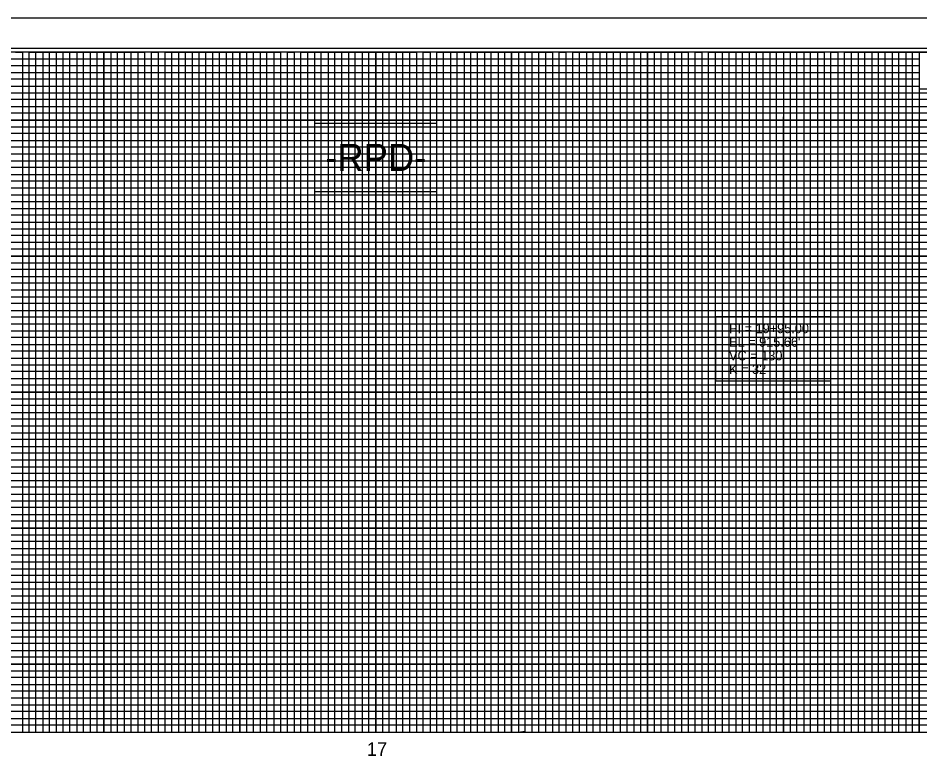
# Model space of a CAD drawing. Extents: x 1648862 to 1650889, y 802691 to 803791.
# Drawn here: x 1649516 to 1650180, y 803245 to 803791 of the extents above; entities that cross this region are included whole.
import ezdxf

# ---------------------------------------------------------------- set-up
doc = ezdxf.new("R2010")
doc.units = 0
for name, color, linetype in [('Exist Vertical Profile Horizontal Axis Label Major', 7, 'Continuous'), ('Prop Dimension Text', 7, 'Continuous'), ('Prop Grid Mask', 7, 'Continuous'), ('Prop Vertical Profile Curve Label', 7, 'Continuous'), ('Prop VPI Label', 7, 'Continuous'), ('Sheet Cutting Line CELL', 7, 'Continuous'), ('Sheet DOT Grid CELL', 7, 'Continuous'), ('Sheet Layout Profile Border Port 1', 7, 'Continuous'), ('Sheet Plot Border Inside CELL', 7, 'Continuous'), ('Sheet Plot Border Outside CELL', 7, 'Continuous'), ('Sheet Profile CELL', 7, 'Continuous'), ('Sheet Profile Grid Major CELL', 7, 'Continuous'), ('Sheet Profile Grid Middle CELL', 7, 'Continuous'), ('Sheet Profile Grid Minor CELL', 7, 'Continuous')]:
    doc.layers.add(name, color=color, linetype=linetype)

msp = doc.modelspace()

# ---------------------------------------------------------------- linework, layer by layer
at = {"layer": 'Prop Dimension Text'}
msp.add_lwpolyline([(1650179.28, 803738.96), (1650329.23, 803738.96), (1650329.23, 803766.02), (1650179.28, 803766.02)], close=True, dxfattribs=at)
at = {"layer": 'Prop Grid Mask'}
for points in [[(1649734.28, 803713.52), (1649734.28, 803663.52), (1649824.28, 803663.52), (1649824.28, 803713.52)], [(1650029.28, 803571.32), (1650029.28, 803524.32), (1650114.09, 803524.32), (1650114.09, 803571.32)]]:
    msp.add_lwpolyline(points, close=True, dxfattribs=at)
at = {"layer": 'Sheet Cutting Line CELL'}
msp.add_line((1650546.28, 803791.02), (1648862.28, 803791.02), dxfattribs=at)
at = {"layer": 'Sheet DOT Grid CELL'}
for p, q in [((1649529.28, 803266.02), (1649529.28, 803766.02)), ((1649579.28, 803266.02), (1649579.28, 803766.02)), ((1649629.28, 803266.02), (1649629.28, 803766.02)), ((1649679.28, 803266.02), (1649679.28, 803766.02)), ((1649729.28, 803266.02), (1649729.28, 803766.02)), ((1649779.28, 803266.02), (1649779.28, 803766.02)), ((1649829.28, 803266.02), (1649829.28, 803766.02)), ((1649879.28, 803266.02), (1649879.28, 803766.02)), ((1649929.28, 803266.02), (1649929.28, 803766.02)), ((1649979.28, 803266.02), (1649979.28, 803766.02)), ((1650029.28, 803266.02), (1650029.28, 803766.02)), ((1650329.23, 803716.02), (1649029.28, 803716.02)), ((1650079.28, 803266.02), (1650079.28, 803718.48)), ((1650129.28, 803266.02), (1650129.28, 803718.48)), ((1650179.28, 803266.02), (1650179.28, 803716.02)), ((1650329.23, 803666.02), (1649029.28, 803666.02)), ((1650329.28, 803616.02), (1649029.28, 803616.02)), ((1650529.28, 803566.02), (1649029.28, 803566.02)), ((1650529.28, 803516.02), (1649029.28, 803516.02)), ((1650529.28, 803466.02), (1649029.28, 803466.02)), ((1650529.28, 803416.02), (1649029.28, 803416.02)), ((1650529.28, 803366.02), (1649029.28, 803366.02)), ((1650529.28, 803316.02), (1649029.28, 803316.02))]:
    msp.add_line(p, q, dxfattribs=at)
at = {"layer": 'Sheet Layout Profile Border Port 1'}
msp.add_lwpolyline([(1649079.28, 803604.97), (1649079.28, 803266.02), (1650479.28, 803266.02), (1650479.28, 803604.97)], dxfattribs=at)
at = {"layer": 'Sheet Plot Border Inside CELL'}
msp.add_lwpolyline([(1648875.28, 802713.47), (1650541.78, 802713.47), (1650541.78, 803768.57), (1648875.28, 803768.57)], close=True, dxfattribs=at)
at = {"layer": 'Sheet Plot Border Outside CELL'}
msp.add_lwpolyline([(1648862.28, 802691.02), (1650546.28, 802691.02), (1650546.28, 803791.02), (1648862.28, 803791.02)], close=True, dxfattribs=at)
at = {"layer": 'Sheet Profile CELL'}
msp.add_line((1649029.28, 803266.02), (1650529.28, 803266.02), dxfattribs=at)
msp.add_lwpolyline([(1650529.28, 803766.02), (1649029.28, 803766.02), (1649029.28, 802716.02), (1650529.28, 802716.02)], close=True, dxfattribs=at)
at = {"layer": 'Sheet Profile Grid Major CELL'}
for points in [[(1649479.28, 803266.02), (1649529.28, 803266.02), (1649529.28, 803766.02), (1649579.28, 803766.02), (1649579.28, 803266.02), (1649629.28, 803266.02), (1649629.28, 803766.02), (1649679.28, 803766.02), (1649679.28, 803266.02), (1649729.28, 803266.02), (1649729.28, 803766.02), (1649779.28, 803766.02), (1649779.28, 803266.02), (1649829.28, 803266.02), (1649829.28, 803766.02), (1649879.28, 803766.02), (1649879.28, 803266.02), (1649929.28, 803266.02), (1649929.28, 803766.02), (1649979.28, 803766.02), (1649979.28, 803266.02), (1650029.28, 803266.02), (1650029.28, 803766.02), (1650079.28, 803766.02), (1650079.28, 803266.02), (1650129.28, 803266.02), (1650129.28, 803766.02), (1650179.28, 803766.02), (1650179.28, 803266.02), (1650229.28, 803266.02)], [(1649029.28, 803716.02), (1650329.28, 803716.02)], [(1650329.28, 803666.02), (1649029.28, 803666.02), (1649029.28, 803616.02), (1650329.28, 803616.02)], [(1650529.28, 803566.02), (1649029.28, 803566.02), (1649029.28, 803516.02), (1650529.28, 803516.02)], [(1650529.28, 803466.02), (1649029.28, 803466.02), (1649029.28, 803416.02), (1650529.28, 803416.02)], [(1650529.28, 803366.02), (1649029.28, 803366.02), (1649029.28, 803366.02), (1649029.28, 803316.02), (1650529.28, 803316.02)]]:
    msp.add_lwpolyline(points, dxfattribs=at)
at = {"layer": 'Sheet Profile Grid Middle CELL'}
msp.add_line((1649029.28, 803741.02), (1650179.28, 803741.02), dxfattribs=at)
for points in [[(1649504.28, 803266.02), (1649554.28, 803266.02), (1649554.28, 803766.02), (1649604.28, 803766.02), (1649604.28, 803266.02), (1649654.28, 803266.02), (1649654.28, 803266.02), (1649654.28, 803766.02), (1649704.28, 803766.02), (1649704.28, 803266.02), (1649754.28, 803266.02), (1649754.28, 803766.02), (1649804.28, 803766.02), (1649804.28, 803266.02), (1649854.28, 803266.02), (1649854.28, 803766.02), (1649904.28, 803766.02), (1649904.28, 803266.02), (1649954.28, 803266.02), (1649954.28, 803766.02), (1650004.28, 803766.02), (1650004.28, 803266.02), (1650054.28, 803266.02), (1650054.28, 803766.02), (1650104.28, 803766.02), (1650104.28, 803266.02), (1650154.28, 803266.02), (1650154.28, 803766.02), (1650204.28, 803766.02)], [(1650329.28, 803691.02), (1649029.28, 803691.02), (1649029.28, 803641.02), (1650329.28, 803641.02)], [(1650529.28, 803591.02), (1649029.28, 803591.02), (1649029.28, 803541.02), (1650354.28, 803541.02)], [(1650529.28, 803491.02), (1649029.28, 803491.02), (1649029.28, 803441.02), (1650529.28, 803441.02)], [(1650529.28, 803391.02), (1649029.28, 803391.02), (1649029.28, 803341.02), (1650529.28, 803341.02)], [(1650529.28, 803291.02), (1649029.28, 803291.02)]]:
    msp.add_lwpolyline(points, dxfattribs=at)
at = {"layer": 'Sheet Profile Grid Minor CELL'}
for p, q in [((1649079.28, 803761.02), (1650179.28, 803761.02)), ((1649614.28, 803766.02), (1649619.28, 803766.02)), ((1649624.28, 803766.02), (1649634.28, 803766.02)), ((1649639.28, 803766.02), (1649644.28, 803766.02)), ((1649649.28, 803766.02), (1649659.28, 803766.02)), ((1649664.28, 803766.02), (1649669.28, 803766.02)), ((1649674.28, 803766.02), (1649684.28, 803766.02)), ((1649689.28, 803766.02), (1649694.28, 803766.02)), ((1649699.28, 803766.02), (1649709.28, 803766.02)), ((1649714.28, 803766.02), (1649719.28, 803766.02)), ((1649724.28, 803766.02), (1649734.28, 803766.02)), ((1649739.28, 803766.02), (1649744.28, 803766.02)), ((1649749.28, 803766.02), (1649759.28, 803766.02)), ((1649764.28, 803766.02), (1649769.28, 803766.02)), ((1649774.28, 803766.02), (1649784.28, 803766.02)), ((1649789.28, 803766.02), (1649794.28, 803766.02)), ((1649799.28, 803766.02), (1649809.28, 803766.02)), ((1649814.28, 803766.02), (1649819.28, 803766.02)), ((1649824.28, 803766.02), (1649834.28, 803766.02)), ((1649839.28, 803766.02), (1649844.28, 803766.02)), ((1649849.28, 803766.02), (1649859.28, 803766.02)), ((1649864.28, 803766.02), (1649869.28, 803766.02)), ((1649874.28, 803766.02), (1649884.28, 803766.02)), ((1649889.28, 803766.02), (1649894.28, 803766.02)), ((1649899.28, 803766.02), (1649909.28, 803766.02)), ((1650179.28, 803755.98), (1649079.28, 803755.67)), ((1649079.28, 803751.02), (1650179.28, 803751.02)), ((1650329.23, 803631.02), (1649079.28, 803631.02)), ((1650329.28, 803626.02), (1649079.28, 803626.02)), ((1650329.28, 803621.02), (1649079.28, 803621.02)), ((1649079.28, 803611.02), (1650329.28, 803611.02)), ((1650329.28, 803606.02), (1649079.28, 803606.02)), ((1649079.28, 803601.02), (1650479.28, 803601.02)), ((1650479.28, 803581.02), (1649079.28, 803581.02)), ((1649079.28, 803576.02), (1650479.28, 803576.02)), ((1650479.28, 803556.02), (1649079.28, 803556.02)), ((1649079.28, 803551.02), (1650479.28, 803551.02)), ((1650479.28, 803531.02), (1649079.28, 803531.02)), ((1649079.28, 803526.02), (1650479.28, 803526.02)), ((1650479.28, 803521.02), (1649079.28, 803521.02)), ((1649079.28, 803511.02), (1650479.28, 803511.02)), ((1650479.28, 803506.02), (1649079.28, 803506.02)), ((1649079.28, 803501.02), (1650479.28, 803501.02)), ((1650479.28, 803496.02), (1649079.28, 803496.02)), ((1649079.28, 803486.02), (1650479.28, 803486.02)), ((1650479.28, 803481.02), (1649079.28, 803481.02)), ((1649079.28, 803476.02), (1650479.28, 803476.02)), ((1650479.28, 803471.02), (1649079.28, 803471.02)), ((1649079.28, 803461.02), (1650479.28, 803461.02)), ((1650479.28, 803456.02), (1649079.28, 803456.02)), ((1649079.28, 803451.02), (1650479.28, 803451.02)), ((1650479.28, 803446.02), (1649079.28, 803446.02)), ((1649079.28, 803436.02), (1650479.28, 803436.02)), ((1650479.28, 803431.02), (1649079.28, 803431.02)), ((1649079.28, 803426.02), (1650479.28, 803426.02)), ((1650479.28, 803421.02), (1649079.28, 803421.02)), ((1649079.28, 803411.02), (1650479.28, 803411.02)), ((1650479.28, 803406.02), (1649079.28, 803406.02)), ((1649079.28, 803401.02), (1650479.28, 803401.02)), ((1650479.28, 803396.02), (1649079.28, 803396.02)), ((1649079.28, 803386.02), (1650479.28, 803386.02)), ((1650479.28, 803381.02), (1649079.28, 803381.02)), ((1650479.28, 803376.02), (1649079.28, 803376.02)), ((1650479.28, 803371.02), (1649079.28, 803371.02)), ((1649079.28, 803361.02), (1650479.28, 803361.02)), ((1650479.28, 803356.02), (1649079.28, 803356.02)), ((1649079.28, 803351.02), (1650479.28, 803351.02)), ((1650479.28, 803346.02), (1649079.28, 803346.02)), ((1649079.28, 803336.02), (1650479.28, 803336.02)), ((1650479.28, 803331.02), (1649079.28, 803331.02)), ((1649079.28, 803326.02), (1650479.28, 803326.02)), ((1650479.28, 803321.02), (1649079.28, 803321.02)), ((1649079.28, 803311.02), (1650479.28, 803311.02)), ((1650479.28, 803306.02), (1649079.28, 803306.02)), ((1649079.28, 803301.02), (1650479.28, 803301.02)), ((1650479.28, 803296.02), (1649079.28, 803296.02)), ((1649079.28, 803286.02), (1650479.28, 803286.02)), ((1650479.28, 803281.02), (1649079.28, 803281.02)), ((1649079.28, 803276.02), (1650479.28, 803276.02)), ((1649609.28, 803266.02), (1649614.28, 803266.02)), ((1649619.28, 803266.02), (1649624.28, 803266.02)), ((1649634.28, 803266.02), (1649639.28, 803266.02)), ((1649644.28, 803266.02), (1649649.28, 803266.02)), ((1649659.28, 803266.02), (1649664.28, 803266.02)), ((1649669.28, 803266.02), (1649674.28, 803266.02)), ((1649684.28, 803266.02), (1649689.28, 803266.02)), ((1649694.28, 803266.02), (1649699.28, 803266.02)), ((1649709.28, 803266.02), (1649714.28, 803266.02)), ((1649719.28, 803266.02), (1649724.28, 803266.02)), ((1649734.28, 803266.02), (1649734.28, 803266.02)), ((1649734.28, 803266.02), (1649739.28, 803266.02)), ((1649744.28, 803266.02), (1649749.28, 803266.02)), ((1649759.28, 803266.02), (1649764.28, 803266.02)), ((1649769.28, 803266.02), (1649774.28, 803266.02)), ((1649784.28, 803266.02), (1649789.28, 803266.02)), ((1649794.28, 803266.02), (1649799.28, 803266.02)), ((1649809.28, 803266.02), (1649814.28, 803266.02)), ((1649819.28, 803266.02), (1649824.28, 803266.02)), ((1649834.28, 803266.02), (1649839.28, 803266.02)), ((1649844.28, 803266.02), (1649849.28, 803266.02)), ((1649859.28, 803266.02), (1649864.28, 803266.02)), ((1649869.28, 803266.02), (1649874.28, 803266.02)), ((1649884.28, 803266.02), (1649888.98, 803266.57)), ((1649888.98, 803266.57), (1649889.28, 803266.02)), ((1649894.28, 803266.02), (1649899.28, 803266.02)), ((1649909.28, 803266.02), (1649914.28, 803266.02)), ((1650159.28, 803266.02), (1650164.28, 803266.02))]:
    msp.add_line(p, q, dxfattribs=at)
for points in [[(1649514.28, 803766.02), (1649519.28, 803766.02), (1649519.28, 803266.02), (1649524.28, 803266.02), (1649524.28, 803766.02), (1649534.28, 803766.02), (1649534.28, 803266.02), (1649539.28, 803266.02), (1649539.28, 803766.02), (1649544.28, 803766.02), (1649544.28, 803266.02), (1649549.28, 803266.02), (1649549.28, 803766.02), (1649559.28, 803766.02), (1649559.28, 803266.02), (1649564.28, 803266.02), (1649564.28, 803766.02), (1649569.28, 803766.02), (1649569.28, 803266.02), (1649574.28, 803266.02), (1649574.28, 803766.02), (1649584.28, 803766.02), (1649584.28, 803266.02), (1649589.28, 803266.02), (1649589.28, 803766.02), (1649594.28, 803766.02), (1649594.28, 803266.02), (1649599.28, 803266.02), (1649599.28, 803766.02), (1649609.28, 803766.02)], [(1649609.28, 803766.02), (1649609.28, 803266.02), (1649614.28, 803266.02), (1649614.28, 803766.02), (1649619.28, 803766.02), (1649619.28, 803266.02), (1649624.28, 803266.02), (1649624.28, 803766.02), (1649634.28, 803766.02), (1649634.28, 803266.02), (1649639.28, 803266.02), (1649639.28, 803766.02), (1649644.28, 803766.02), (1649644.28, 803266.02), (1649649.28, 803266.02), (1649649.28, 803766.02), (1649659.28, 803766.02), (1649659.28, 803266.02), (1649664.28, 803266.02), (1649664.28, 803766.02), (1649669.28, 803766.02), (1649669.28, 803266.02), (1649674.28, 803266.02), (1649674.28, 803766.02), (1649684.28, 803766.02), (1649684.28, 803266.02), (1649689.28, 803266.02), (1649689.28, 803766.02), (1649694.28, 803766.02), (1649694.28, 803266.02), (1649699.28, 803266.02), (1649699.28, 803766.02), (1649709.28, 803766.02), (1649709.28, 803266.02), (1649714.28, 803266.02), (1649714.28, 803766.02), (1649719.28, 803766.02), (1649719.28, 803266.02), (1649724.28, 803266.02), (1649724.28, 803766.02), (1649734.28, 803766.02), (1649734.28, 803266.02), (1649734.28, 803266.02), (1649739.28, 803266.02), (1649739.28, 803766.02), (1649744.28, 803766.02), (1649744.28, 803266.02), (1649749.28, 803266.02), (1649749.28, 803766.02), (1649759.28, 803766.02), (1649759.28, 803266.02), (1649764.28, 803266.02), (1649764.28, 803766.02), (1649769.28, 803766.02), (1649769.28, 803266.02), (1649774.28, 803266.02), (1649774.28, 803766.02), (1649784.28, 803766.02), (1649784.28, 803266.02), (1649789.28, 803266.02), (1649789.28, 803766.02), (1649794.28, 803766.02), (1649794.28, 803266.02), (1649799.28, 803266.02), (1649799.28, 803766.02), (1649809.28, 803766.02), (1649809.28, 803266.02), (1649814.28, 803266.02), (1649814.28, 803766.02), (1649819.28, 803766.02), (1649819.28, 803266.02), (1649824.28, 803266.02), (1649824.28, 803766.02), (1649834.28, 803766.02), (1649834.28, 803266.02), (1649839.28, 803266.02), (1649839.28, 803766.02), (1649844.28, 803766.02), (1649844.28, 803266.02), (1649849.28, 803266.02), (1649849.28, 803766.02), (1649859.28, 803766.02), (1649859.28, 803266.02), (1649864.28, 803266.02), (1649864.28, 803766.02), (1649869.28, 803766.02), (1649869.28, 803266.02), (1649874.28, 803266.02), (1649874.28, 803766.02), (1649884.28, 803766.02), (1649884.28, 803266.02), (1649888.98, 803266.57), (1649889.28, 803266.02), (1649889.28, 803766.02), (1649894.28, 803766.02), (1649894.28, 803266.02), (1649899.28, 803266.02), (1649899.28, 803766.02), (1649909.28, 803766.02), (1649909.28, 803266.02), (1649914.28, 803266.02)], [(1649914.28, 803266.02), (1649914.28, 803766.02), (1649919.28, 803766.02), (1649919.28, 803266.02), (1649924.28, 803266.02), (1649924.28, 803766.02), (1649934.28, 803766.02), (1649934.28, 803266.02), (1649939.28, 803266.02), (1649939.28, 803766.02), (1649944.28, 803766.02), (1649944.28, 803266.02), (1649949.28, 803266.02), (1649949.28, 803766.02), (1649959.28, 803766.02), (1649959.28, 803266.02), (1649964.28, 803266.02), (1649964.28, 803766.02), (1649969.28, 803766.02), (1649969.28, 803266.02), (1649974.28, 803266.02), (1649974.28, 803766.02), (1649984.28, 803766.02), (1649984.28, 803266.02), (1649989.28, 803266.02), (1649989.28, 803766.02), (1649994.28, 803766.02), (1649994.28, 803266.02), (1649999.28, 803266.02), (1649999.28, 803766.02), (1650009.28, 803766.02), (1650009.28, 803266.02), (1650014.28, 803266.02), (1650014.28, 803766.02), (1650019.28, 803766.02), (1650019.28, 803266.02), (1650024.28, 803266.02), (1650024.28, 803766.02), (1650034.28, 803766.02), (1650034.28, 803266.02), (1650039.28, 803266.02), (1650039.28, 803766.02), (1650044.28, 803766.02), (1650044.28, 803266.02), (1650049.28, 803266.02), (1650049.28, 803766.02), (1650059.28, 803766.02), (1650059.28, 803266.02), (1650064.28, 803266.02), (1650064.28, 803766.02), (1650069.28, 803766.02), (1650069.28, 803266.02), (1650074.28, 803266.02), (1650074.28, 803766.02), (1650084.28, 803766.02), (1650084.28, 803266.02), (1650089.28, 803266.02), (1650089.28, 803766.02), (1650094.28, 803766.02), (1650094.28, 803266.02), (1650099.28, 803266.02), (1650099.28, 803766.02), (1650109.28, 803766.02), (1650109.28, 803266.02), (1650114.28, 803266.02), (1650114.28, 803766.02), (1650119.28, 803766.02), (1650119.28, 803266.02), (1650124.28, 803266.02), (1650124.28, 803766.02), (1650134.28, 803766.02), (1650134.28, 803266.02), (1650139.28, 803266.02), (1650139.28, 803766.02), (1650144.28, 803766.02), (1650144.28, 803266.02), (1650149.28, 803266.02), (1650149.28, 803766.02), (1650159.28, 803766.02), (1650159.28, 803266.02), (1650164.28, 803266.02), (1650164.28, 803766.02), (1650169.28, 803766.02), (1650169.28, 803266.02), (1650174.28, 803266.02), (1650174.28, 803766.02), (1650184.28, 803766.02)], [(1650179.28, 803746.02), (1649079.28, 803746.02), (1649079.28, 803736.02), (1650329.28, 803736.02)], [(1650329.23, 803731.02), (1649079.28, 803731.02), (1649079.28, 803726.02), (1650329.28, 803726.02)], [(1650329.28, 803721.02), (1649079.28, 803721.02), (1649079.28, 803711.02), (1650329.28, 803711.02)], [(1650329.28, 803706.02), (1649079.28, 803706.02), (1649079.28, 803701.02), (1650329.28, 803701.02)], [(1650329.28, 803696.02), (1649079.28, 803696.02), (1649079.28, 803686.02), (1650329.28, 803686.02)], [(1650329.28, 803681.02), (1649079.28, 803681.02), (1649079.28, 803676.02), (1650329.28, 803676.02)], [(1650329.28, 803671.02), (1649079.28, 803671.02), (1649079.28, 803661.02), (1650329.28, 803661.02)], [(1650329.28, 803655.92), (1649079.38, 803655.92), (1649079.38, 803651.02), (1650329.28, 803651.02)], [(1650329.28, 803646.02), (1649079.28, 803646.02), (1649079.28, 803636.02), (1650329.28, 803636.02)], [(1650479.28, 803596.02), (1649079.28, 803596.02), (1649079.28, 803586.02), (1650479.28, 803586.02)], [(1650479.28, 803571.02), (1649079.28, 803571.02), (1649079.28, 803561.02), (1650479.28, 803561.02)], [(1650479.28, 803546.02), (1649079.28, 803546.02), (1649079.28, 803536.02), (1650479.28, 803536.02)], [(1650479.28, 803271.02), (1649079.28, 803271.02)], [(1650479.28, 803271.02), (1649079.28, 803271.02)]]:
    msp.add_lwpolyline(points, dxfattribs=at)

# ---------------------------------------------------------------- texts
at = {"layer": 'Exist Vertical Profile Horizontal Axis Label Major'}
for s, height, p in [('-RPD-', 20, (1649742.21, 803678.52)), ('17', 10, (1649772.82, 803248.52))]:
    msp.add_text(s, height=height, dxfattribs=at).set_placement(p)
at = {"layer": 'Prop Vertical Profile Curve Label'}
for s, p in [("VC = 130'", (1650039.28, 803539.32)), ('K = 32', (1650039.28, 803529.32))]:
    msp.add_text(s, height=7, dxfattribs=at).set_placement(p)
at = {"layer": 'Prop VPI Label'}
for s, p in [('PI = 19+95.00', (1650039.28, 803559.32)), ("EL = 915.66'", (1650039.28, 803549.32))]:
    msp.add_text(s, height=7, dxfattribs=at).set_placement(p)

doc.saveas('drawing.dxf')
